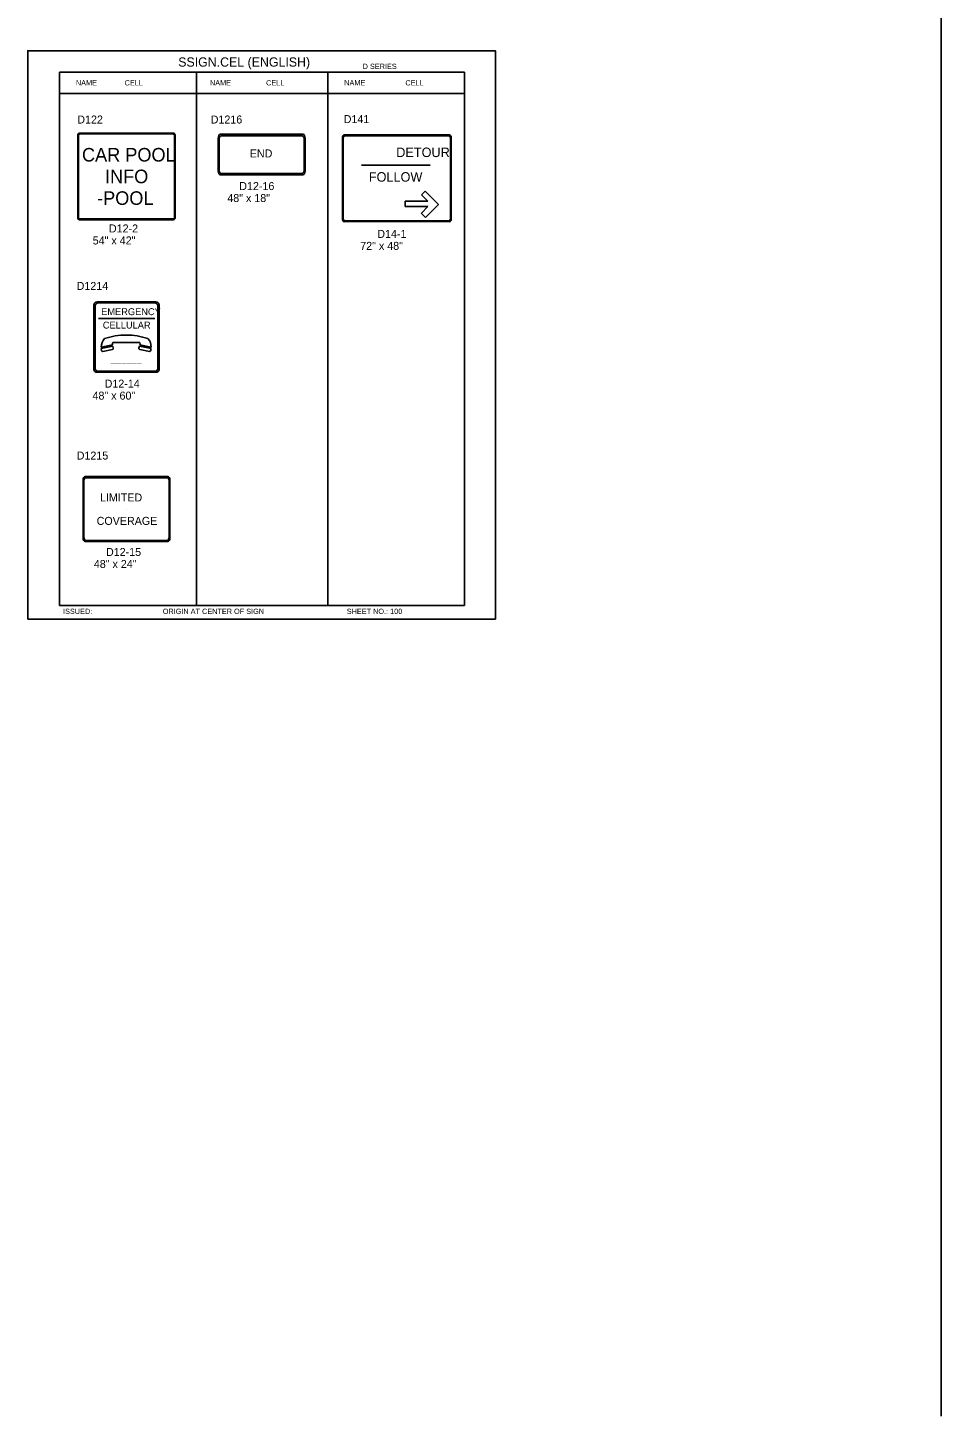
# Model space of a CAD drawing. Extents: x -5299 to 22597, y -19549 to -1808.
# Drawn here: x 12315 to 13684, y -9426 to -7343 of the extents above; entities that cross this region are included whole.
import ezdxf

# ---------------------------------------------------------------- set-up
doc = ezdxf.new("R2010")
doc.units = 0
for name, color, linetype in [('Level 1', 7, 'Continuous'), ('Level 2', 7, 'Continuous'), ('Level 3', 7, 'Continuous'), ('Level 61', 7, 'Continuous')]:
    doc.layers.add(name, color=color, linetype=linetype)

msp = doc.modelspace()

# ---------------------------------------------------------------- linework, layer by layer
at = {"layer": 'Level 1'}
for p, q in [((12969.5, -7410), (12362.4, -7410)), ((12362.4, -7410), (12362.4, -8210)), ((12568.1, -7410), (12568.1, -8210)), ((12764.9, -7410), (12764.9, -8210)), ((12969.5, -7410), (12969.5, -8210)), ((12969.5, -7441.7), (12362.4, -7441.7)), ((12389.8, -7628), (12389.8, -7504.5)), ((12390.8, -7627.1), (12390.8, -7505.5)), ((12392.7, -7501.2), (12533.1, -7501.2)), ((12393.5, -7502.4), (12532.3, -7502.4)), ((12535, -7505.5), (12535, -7627.1)), ((12536.1, -7504.5), (12536.1, -7628)), ((12600.6, -7532.4), (12600.6, -7509)), ((12601.8, -7532.4), (12601.8, -7510.8)), ((12603.8, -7503.1), (12727.4, -7503.1)), ((12604.8, -7505.3), (12726.4, -7505.3)), ((12729.4, -7510.8), (12729.4, -7532.4)), ((12730.6, -7509), (12730.6, -7532.4)), ((12786.9, -7630.9), (12786.9, -7507.3)), ((12787.9, -7629.9), (12787.9, -7508.3)), ((12789.6, -7504.1), (12947, -7504.1)), ((12790.4, -7505.3), (12946.2, -7505.3)), ((12948.7, -7508.3), (12948.7, -7629.9)), ((12949.8, -7507.3), (12949.8, -7630.9)), ((12600.6, -7558.1), (12600.6, -7532.4)), ((12601.8, -7556.3), (12601.8, -7532.4)), ((12665.6, -7532.4), (12665.6, -7532.4)), ((12729.4, -7532.4), (12729.4, -7556.3)), ((12730.6, -7532.4), (12730.6, -7558.1)), ((12815.2, -7549.4), (12918.3, -7549.4)), ((12462.9, -7566.3), (12462.9, -7566.3)), ((12727.4, -7564.1), (12603.8, -7564.1)), ((12726.4, -7561.8), (12604.8, -7561.8)), ((12868, -7569.4), (12868, -7569.4)), ((12533.1, -7631.3), (12392.7, -7631.3)), ((12532.3, -7630.1), (12393.5, -7630.1)), ((12947, -7634.1), (12789.6, -7634.1)), ((12946.2, -7632.9), (12790.4, -7632.9)), ((12414.1, -7855.8), (12414.1, -7758.6)), ((12415.9, -7854.6), (12415.9, -7759.9)), ((12419, -7754.4), (12506.8, -7754.4)), ((12420.5, -7755.9), (12505.3, -7755.9)), ((12509.9, -7759.9), (12509.9, -7854.6)), ((12511.7, -7758.6), (12511.7, -7855.8)), ((12421.1, -7779.4), (12505.6, -7779.4)), ((12462.9, -7807.2), (12462.9, -7807.2)), ((12442.4, -7820.8), (12424.9, -7824.5)), ((12424.9, -7824.5), (12425.7, -7827.6)), ((12442.2, -7818.6), (12425.1, -7822.2)), ((12427.5, -7828.8), (12442, -7825.7)), ((12441.8, -7817.1), (12442.2, -7818.6)), ((12443.2, -7823.9), (12442.4, -7820.8)), ((12481.8, -7815.2), (12443, -7815.2)), ((12481.6, -7823.9), (12482.4, -7820.8)), ((12482.4, -7820.8), (12499.9, -7824.5)), ((12497.3, -7828.8), (12482.8, -7825.7)), ((12482.9, -7818.6), (12483.3, -7817.1)), ((12500, -7822.2), (12482.9, -7818.6)), ((12499.9, -7824.5), (12499.1, -7827.6)), ((12506.8, -7860), (12419, -7860)), ((12505.3, -7858.5), (12420.5, -7858.5)), ((12401.1, -8016.3), (12524.7, -8016.3)), ((12397.9, -8109), (12397.9, -8021.2)), ((12399.1, -8107.6), (12399.1, -8022.6)), ((12402.1, -8018.1), (12523.8, -8018.1)), ((12526.7, -8022.6), (12526.7, -8107.6)), ((12528, -8021.2), (12528, -8109)), ((12462.9, -8065.1), (12462.9, -8065.1)), ((12524.7, -8113.9), (12401.1, -8113.9)), ((12523.8, -8112.1), (12402.1, -8112.1)), ((12362.4, -8210), (12969.5, -8210))]:
    msp.add_line(p, q, dxfattribs=at)
for centre, radius, start, end in [((12462.6, -7907.2), 103, 71.5623, 108.4377), ((12444.3, -7822.2), 19.2, 138.2555, 180.107), ((12427.2, -7827.3), 1.52, 191.8786, 281.8845), ((12443.3, -7816.7), 1.52, 90, 194.0392), ((12441.7, -7824.3), 1.52, 281.5026, 14.0362), ((12483.1, -7824.3), 1.52, 165.9638, 258.4974), ((12481.8, -7816.7), 1.52, 345.9699, 90), ((12480.8, -7822.2), 19.2, 359.893, 41.7445), ((12497.6, -7827.3), 1.52, 258.1155, 348.1214)]:
    msp.add_arc(centre, radius, start, end, dxfattribs=at)
for centre, major_axis, ratio, start_param, end_param in [((12392.7, -7504.5), (0, -3.25), 0.9, 3.141593, 4.712389), ((12393.5, -7505.5), (0, -3.01), 0.9, 3.141593, 4.712389), ((12532.3, -7505.5), (0, 3.01), 0.9, 4.712389, 6.283185), ((12533.1, -7504.5), (0, 3.25), 0.9, 4.712389, 6.283185), ((12603.8, -7509), (0, -5.96), 0.545182, 3.141593, 4.712389), ((12604.8, -7510.8), (0, -5.52), 0.545182, 3.141593, 4.712389), ((12726.4, -7510.8), (0, 5.52), 0.545182, 4.712389, 6.283185), ((12727.4, -7509), (0, 5.96), 0.545182, 4.712389, 6.283185), ((12789.6, -7507.3), (0, -3.25), 0.83475, 3.141593, 4.712389), ((12790.4, -7508.3), (0, -3.01), 0.83475, 3.141593, 4.712389), ((12946.2, -7508.3), (0, 3.01), 0.83475, 4.712389, 6.283185), ((12947, -7507.3), (0, 3.25), 0.83475, 4.712389, 6.283185), ((12603.8, -7558.1), (0, -5.96), 0.545182, 4.712389, 6.283185), ((12604.8, -7556.3), (0, -5.52), 0.545182, 4.712389, 6.283185), ((12726.4, -7556.3), (0, 5.52), 0.545182, 3.141593, 4.712389), ((12727.4, -7558.1), (0, 5.96), 0.545182, 3.141593, 4.712389), ((12392.7, -7628), (0, -3.25), 0.9, 4.712389, 6.283185), ((12393.5, -7627.1), (0, -3.01), 0.9, 4.712389, 6.283185), ((12532.3, -7627.1), (0, 3.01), 0.9, 3.141593, 4.712389), ((12533.1, -7628), (0, 3.25), 0.9, 3.141593, 4.712389), ((12789.6, -7630.9), (0, -3.25), 0.83475, 4.712389, 6.283185), ((12790.4, -7629.9), (0, -3.01), 0.83475, 4.712389, 6.283185), ((12946.2, -7629.9), (0, 3.01), 0.83475, 3.141593, 4.712389), ((12947, -7630.9), (0, 3.25), 0.83475, 3.141593, 4.712389), ((12419, -7758.6), (-4.88, 0), 0.866667, 4.712389, 6.283185), ((12420.5, -7759.9), (-4.51, 0), 0.866667, 4.712389, 6.283185), ((12505.3, -7759.9), (4.51, 0), 0.866667, 0, 1.570796), ((12506.8, -7758.6), (-4.88, 0), 0.866667, 3.141593, 4.712389), ((12419, -7855.8), (4.88, 0), 0.866667, 3.141593, 4.712389), ((12420.5, -7854.6), (4.51, 0), 0.866667, 3.141593, 4.712389), ((12505.3, -7854.6), (4.51, 0), 0.866667, 4.712389, 6.283185), ((12506.8, -7855.8), (4.88, 0), 0.866667, 4.712389, 6.283185), ((12401.1, -8021.2), (0, 4.88), 0.666667, 0, 1.570796), ((12524.7, -8021.2), (0, 4.88), 0.666667, 4.712389, 6.283185), ((12402.1, -8022.6), (0, 4.47), 0.666667, 0, 1.570796), ((12523.8, -8022.6), (0, 4.47), 0.666667, 4.712389, 6.283185), ((12401.1, -8109), (0, -4.88), 0.666667, 4.712389, 6.283185), ((12402.1, -8107.6), (0, -4.47), 0.666667, 4.712389, 6.283185), ((12523.8, -8107.6), (0, -4.47), 0.666667, 0, 1.570796), ((12524.7, -8109), (0, 4.88), 0.666667, 3.141593, 4.712389)]:
    msp.add_ellipse(centre, major_axis=major_axis, ratio=ratio, start_param=start_param, end_param=end_param, dxfattribs=at)
at = {"layer": 'Level 3'}
for p, q in [((13684.5, -1877.7), (13684.5, -9425.7)), ((12905.2, -7594), (12910.9, -7588.3)), ((12914.8, -7603.5), (12905.2, -7594)), ((12910.9, -7588.3), (12930.9, -7608.2)), ((12880.9, -7611.6), (12880.9, -7603.5)), ((12880.9, -7603.5), (12914.8, -7603.5)), ((12914.8, -7611.6), (12880.9, -7611.6)), ((12911.4, -7627.7), (12905, -7621.3)), ((12905.1, -7621.3), (12914.8, -7611.6)), ((12930.9, -7608.2), (12911.4, -7627.7))]:
    msp.add_line(p, q, dxfattribs=at)
at = {"layer": 'Level 61'}
msp.add_lwpolyline([(12314.9, -8230.2), (13016, -8230.2), (13016, -7377.8), (12314.9, -7377.8)], close=True, dxfattribs=at)

# ---------------------------------------------------------------- texts
at = {"layer": 'Level 1'}
for s, height, p in [('CAR POOL', 20.32, (12396.2, -7543.9)), ('END', 12, (12647.8, -7537.8)), ('DETOUR', 14.22, (12867.4, -7537.2)), ('INFO', 20.32, (12430.7, -7576.4)), ('FOLLOW', 14.22, (12826.3, -7574.1)), ('   -POOL', 20.32, (12396.2, -7608.9)), ('EMERGENCY', 10.37, (12425, -7774.3)), ('CELLULAR', 10.37, (12427.4, -7794.4)), ('______', 10.37, (12439.5, -7844.8)), ('LIMITED', 12, (12423.2, -8053.8)), ('COVERAGE', 12, (12418.2, -8088.9))]:
    msp.add_text(s, height=height, dxfattribs=at).set_placement(p)
at = {"layer": 'Level 2'}
for s, p in [('D122', (12389.2, -7486.9)), ('D1216', (12589.2, -7486.9)), ('D141', (12788.6, -7486.3)), ('D1214', (12388.2, -7736.5)), ('D1215', (12388.3, -7990.9))]:
    msp.add_text(s, height=12, dxfattribs=at).set_placement(p)
at = {"layer": 'Level 3'}
for s, height, p in [('SSIGN.CEL (ENGLISH)', 13.857, (12540.5, -7401.6)), ('D SERIES', 7.92, (12817, -7405.1)), ('NAME', 7.92, (12387.1, -7429.8)), ('CELL', 7.92, (12460.2, -7429.8)), ('NAME', 7.92, (12588.1, -7429.8)), ('CELL', 7.92, (12672.2, -7429.8)), ('NAME', 7.92, (12789.4, -7429.8)), ('CELL', 7.92, (12881.1, -7429.8)), ('D12-16', 12, (12632, -7586.7)), ('48" x 18"', 12, (12614.1, -7604.7)), ('D12-2', 12, (12436.6, -7650.3)), ('54" x 42"', 12, (12412.3, -7668.3)), ('D14-1', 12, (12839, -7658.4)), ('72" x 48"', 12, (12813.4, -7676.4)), ('D12-14', 12, (12430.2, -7883)), ('48" x 60"', 12, (12412, -7901)), ('48" x 24"', 12, (12414, -8153.5)), ('D12-15', 12, (12432.2, -8135.5)), ('ISSUED:', 7.92, (12367.8, -8222.5)), ('ORIGIN AT CENTER OF SIGN', 7.918, (12517.3, -8222.5)), ('SHEET NO.: 100', 7.918, (12793.2, -8222.5))]:
    msp.add_text(s, height=height, dxfattribs=at).set_placement(p)

doc.saveas('drawing.dxf')
